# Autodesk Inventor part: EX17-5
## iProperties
Created: 2006-04
Part Number: EX17-5
Project: EVERGREEN VALLEY COLLEGE
Description: PIN
Document SubType Name: Modeling
Designer: E. MOSS
Authority: MS. TEACHER
Author: E. MOSS
Revision Number: A
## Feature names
1. Extrusion1
